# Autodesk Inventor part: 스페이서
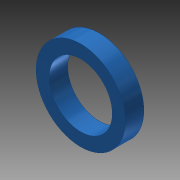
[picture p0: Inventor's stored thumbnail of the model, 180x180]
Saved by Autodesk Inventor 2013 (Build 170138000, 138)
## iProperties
Created: 2018-01
Part Number: 스페이서
Material: 스테인리스강
Document SubType Name: Modeling
Designer: mduedu
Density: 8.08 g/cm^3
Mass: 1.13832 g
Surface Area: 2.73711 cm^2
Volume: 0.140881 cm^3
Author: mduedu
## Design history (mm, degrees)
sketch "스케치1"
  geometry: C1 r 6 at (0, 0); C2 r 4.25 at (0, 0); 1 further point
  constraints: 2 centre point, 2 coincident
  dimensions: "d0" = 12 diameter of C1; "d1" = 8.5 diameter of C2
extrude "돌출1" new body sketch "스케치1" distance "d2" = 2.5; taper "d3" = 0 deg
node "솔리드1"
